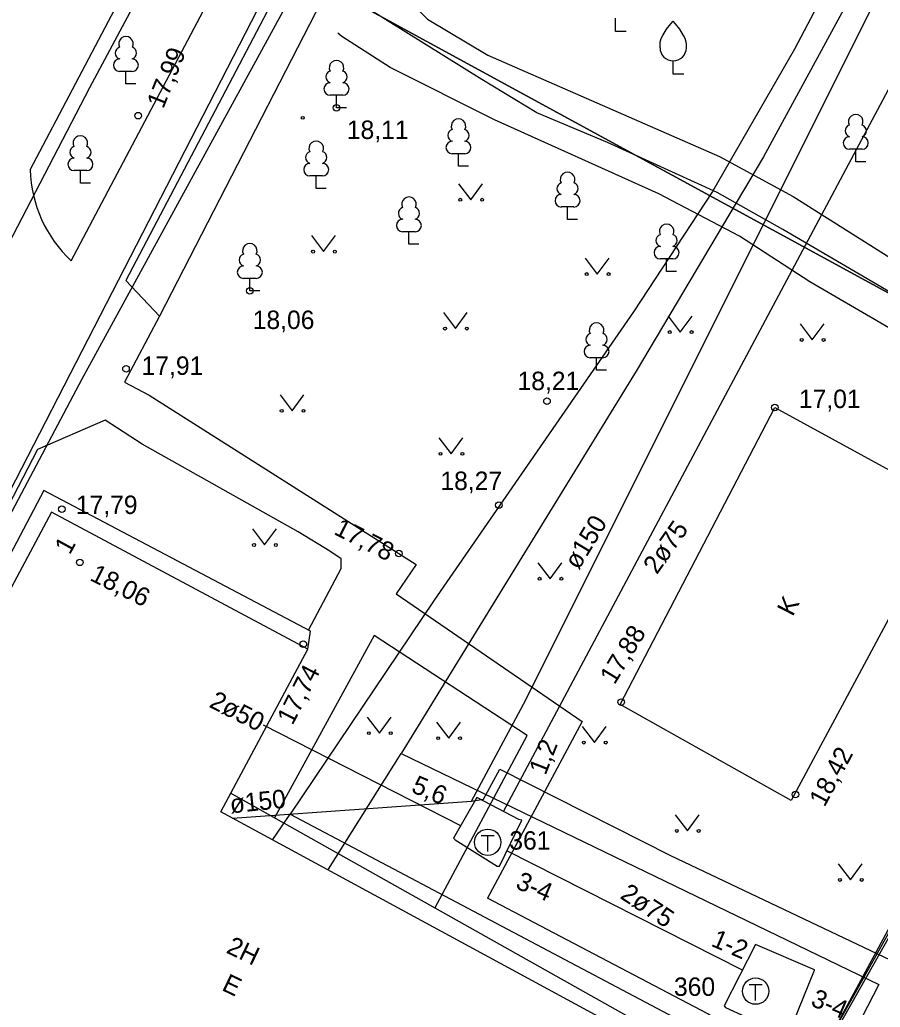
# Model space of a CAD drawing. Extents: x 713540 to 713867, y 6589774 to 6590061.
# Drawn here: x 713743.37 to 713776.03, y 6589910.9 to 6589948.37 of the extents above; entities that cross this region are included whole.
import ezdxf

# ---------------------------------------------------------------- set-up
doc = ezdxf.new("R2010")
doc.units = 0
for name, color, linetype in [('AED', 7, 'Continuous'), ('HALJASTUS', 7, 'Continuous'), ('HOONE', 7, 'Continuous'), ('KORGUS', 7, 'Continuous'), ('MPKAABEL', 7, 'Continuous'), ('PUU', 7, 'Continuous'), ('SIKAEV', 7, 'Continuous'), ('SITRASS', 7, 'Continuous'), ('TEE', 7, 'Continuous'), ('TKAEV', 7, 'Continuous'), ('TORU NR', 7, 'Continuous'), ('TTRASS', 7, 'Continuous'), ('VTRASS', 7, 'Continuous'), ('По умолчанию', 7, 'Continuous'), ('Слой 1', 7, 'Continuous')]:
    doc.layers.add(name, color=color, linetype=linetype)

msp = doc.modelspace()

# ---------------------------------------------------------------- linework, layer by layer
at = {"layer": 'AED'}
for points in [[(713767.762, 6589909.249), (713772.443, 6589906.664), (713772.921, 6589907.533), (713780.72, 6589921.96), (713784.33, 6589929.01), (713786.08, 6589932.05), (713790.79, 6589929.6), (713799.05, 6589941.64), (713799.92, 6589942.78), (713800.93, 6589944.67), (713803.18, 6589949.29), (713806.07, 6589954.43), (713810.4, 6589962.76), (713799.4, 6589967.72), (713795.11, 6589969.78), (713786.56, 6589953.97)], [(713763.714, 6589966.383), (713748.668, 6589937.119)]]:
    msp.add_lwpolyline(points, dxfattribs=at)
at = {"layer": 'HALJASTUS'}
for p, q in [((713760.027, 6589942.147), (713760.49, 6589941.54)), ((713760.49, 6589941.54), (713760.936, 6589942.147)), ((713754.437, 6589940.177), (713754.9, 6589939.57)), ((713754.9, 6589939.57), (713755.346, 6589940.177)), ((713764.827, 6589939.327), (713765.29, 6589938.72)), ((713765.29, 6589938.72), (713765.736, 6589939.327)), ((713759.447, 6589937.257), (713759.91, 6589936.65)), ((713759.91, 6589936.65), (713760.356, 6589937.257)), ((713767.977, 6589937.127), (713768.44, 6589936.52)), ((713768.44, 6589936.52), (713768.886, 6589937.127)), ((713772.987, 6589936.827), (713773.45, 6589936.22)), ((713773.45, 6589936.22), (713773.896, 6589936.827)), ((713753.247, 6589934.137), (713753.71, 6589933.53)), ((713753.71, 6589933.53), (713754.156, 6589934.137)), ((713759.277, 6589932.507), (713759.74, 6589931.9)), ((713759.74, 6589931.9), (713760.186, 6589932.507)), ((713752.197, 6589929.047), (713752.66, 6589928.44)), ((713752.66, 6589928.44), (713753.106, 6589929.047)), ((713763.037, 6589927.767), (713763.5, 6589927.16)), ((713763.5, 6589927.16), (713763.946, 6589927.767)), ((713756.557, 6589921.907), (713757.02, 6589921.3)), ((713757.02, 6589921.3), (713757.466, 6589921.907)), ((713759.187, 6589921.717), (713759.65, 6589921.11)), ((713759.65, 6589921.11), (713760.096, 6589921.717)), ((713764.717, 6589921.547), (713765.18, 6589920.94)), ((713765.18, 6589920.94), (713765.626, 6589921.547)), ((713768.247, 6589918.197), (713768.71, 6589917.59)), ((713768.71, 6589917.59), (713769.156, 6589918.197)), ((713774.437, 6589916.337), (713774.9, 6589915.73)), ((713774.9, 6589915.73), (713775.346, 6589916.337))]:
    msp.add_line(p, q, dxfattribs=at)
for points in [[(713760.304, 6589956.722), (713758.16, 6589952.94), (713757.47, 6589951.68), (713757.33, 6589950.37), (713757.8, 6589949.47), (713758.84, 6589948.39), (713761.14, 6589947.03), (713764.66, 6589945.48), (713769.93, 6589943.18), (713772.72, 6589941.66), (713777.94, 6589938.37), (713784.38, 6589934.37), (713785.89, 6589933.2), (713785.84, 6589932.59), (713785.7, 6589931.83)], [(713784.59, 6589933.17), (713781.02, 6589935.33), (713772.33, 6589940.41), (713769.84, 6589941.82), (713765.68, 6589943.71), (713762.99, 6589944.84), (713760.91, 6589946.1), (713756.58, 6589948.8), (713756.13, 6589949.298)], [(713785.7, 6589931.83), (713779.9, 6589934.62), (713773.36, 6589938.43), (713770.69, 6589940.16), (713767.63, 6589941.77), (713761.39, 6589944.57), (713757.43, 6589946.56), (713755.59, 6589947.74), (713755.446, 6589947.863)]]:
    msp.add_lwpolyline(points, dxfattribs=at)
for centre in [(713760.089, 6589941.54), (713760.918, 6589941.54), (713754.499, 6589939.57), (713755.328, 6589939.57), (713764.889, 6589938.72), (713765.718, 6589938.72), (713759.509, 6589936.65), (713760.338, 6589936.65), (713768.039, 6589936.52), (713768.868, 6589936.52), (713773.049, 6589936.22), (713773.878, 6589936.22), (713753.309, 6589933.53), (713754.138, 6589933.53), (713759.339, 6589931.9), (713760.168, 6589931.9), (713752.259, 6589928.44), (713753.088, 6589928.44), (713763.099, 6589927.16), (713763.928, 6589927.16), (713756.619, 6589921.3), (713757.448, 6589921.3), (713759.249, 6589921.11), (713760.078, 6589921.11), (713764.779, 6589920.94), (713765.608, 6589920.94), (713768.309, 6589917.59), (713769.138, 6589917.59), (713774.499, 6589915.73), (713775.328, 6589915.73)]:
    msp.add_circle(centre, 0.055, dxfattribs=at)
at = {"layer": 'HOONE'}
for points in [[(713760.52, 6589918.72), (713762.58, 6589922.57), (713777.85, 6589953.12)], [(713772.03, 6589933.66), (713778.7, 6589930.01), (713778.64, 6589929.91), (713772.65, 6589918.74), (713766.16, 6589922.39), (713772.03, 6589933.66)], [(713767.753, 6589909.232), (713751, 6589918.31), (713754.305, 6589924.488), (713744.575, 6589929.68), (713736.017, 6589913.674), (713762.631, 6589899.577), (713767.753, 6589909.232)], [(713760.52, 6589918.72), (713760.97, 6589918.8), (713761.59, 6589919.93), (713768.07, 6589916.66), (713778.69, 6589911.61), (713767.43, 6589890.63), (713753, 6589864.84), (713751.627, 6589862.341)], [(713751.44, 6589918.07), (713760.52, 6589918.72)]]:
    msp.add_lwpolyline(points, dxfattribs=at)
at = {"layer": 'KORGUS'}
for centre in [(713755.39, 6589945.03), (713747.86, 6589944.73), (713752.1, 6589938.08), (713747.4, 6589935.12), (713763.38, 6589933.9), (713772.03, 6589933.66), (713761.55, 6589929.95), (713744.96, 6589929.8), (713757.76, 6589928.12), (713745.65, 6589927.78), (713754.13, 6589924.68), (713766.2, 6589922.48), (713772.81, 6589918.97)]:
    msp.add_circle(centre, 0.125, dxfattribs=at)
at = {"layer": 'MPKAABEL'}
for points in [[(713732.905, 6589979.347), (713738.612, 6589976.697), (713744.311, 6589973.432), (713750.492, 6589970.566), (713758.7, 6589965.226), (713761.213, 6589964.896), (713763.366, 6589965.211), (713774.093, 6589959.513), (713777.1, 6589957.91), (713777.68, 6589957.38), (713777.72, 6589957.03), (713777.72, 6589956.58), (713777.41, 6589956.05), (713772.78, 6589947.26), (713769.66, 6589941.85), (713766.66, 6589937.29), (713759.1, 6589926.34), (713753.63, 6589918.22)], [(713753.63, 6589918.22), (713768.19, 6589910.52), (713768.88, 6589910.17), (713769.18, 6589909.51), (713769.069, 6589909.29), (713768.993, 6589909.14), (713753.23, 6589877.99), (713756.95, 6589876.35), (713752.899, 6589868.247), (713751.951, 6589868.518)], [(713752.97, 6589917.26), (713753.63, 6589918.22)]]:
    msp.add_lwpolyline(points, dxfattribs=at)
at = {"layer": 'PUU'}
for p, q in [((713765.98, 6589947.93), (713765.98, 6589948.43)), ((713766.38, 6589947.93), (713765.98, 6589947.93)), ((713768.17, 6589946.31), (713768.17, 6589946.81)), ((713747.637, 6589946.41), (713747.157, 6589946.41)), ((713747.397, 6589945.935), (713747.397, 6589946.41)), ((713768.57, 6589946.31), (713768.17, 6589946.31)), ((713747.777, 6589945.935), (713747.397, 6589945.935)), ((713755.63, 6589945.505), (713755.15, 6589945.505)), ((713755.39, 6589945.03), (713755.39, 6589945.505)), ((713755.77, 6589945.03), (713755.39, 6589945.03)), ((713760.26, 6589943.285), (713759.78, 6589943.285)), ((713760.02, 6589942.81), (713760.02, 6589943.285)), ((713775.34, 6589943.455), (713774.86, 6589943.455)), ((713775.1, 6589942.98), (713775.1, 6589943.455)), ((713760.4, 6589942.81), (713760.02, 6589942.81)), ((713775.48, 6589942.98), (713775.1, 6589942.98)), ((713745.909, 6589942.645), (713745.429, 6589942.645)), ((713745.669, 6589942.17), (713745.669, 6589942.645)), ((713754.86, 6589942.445), (713754.38, 6589942.445)), ((713754.62, 6589941.97), (713754.62, 6589942.445)), ((713746.049, 6589942.17), (713745.669, 6589942.17)), ((713755, 6589941.97), (713754.62, 6589941.97)), ((713764.4, 6589941.265), (713763.92, 6589941.265)), ((713764.16, 6589940.79), (713764.16, 6589941.265)), ((713764.54, 6589940.79), (713764.16, 6589940.79)), ((713758.38, 6589940.325), (713757.9, 6589940.325)), ((713758.14, 6589939.85), (713758.14, 6589940.325)), ((713758.52, 6589939.85), (713758.14, 6589939.85)), ((713768.16, 6589939.295), (713767.68, 6589939.295)), ((713767.92, 6589938.82), (713767.92, 6589939.295)), ((713768.3, 6589938.82), (713767.92, 6589938.82)), ((713752.34, 6589938.555), (713751.86, 6589938.555)), ((713752.1, 6589938.08), (713752.1, 6589938.555)), ((713752.48, 6589938.08), (713752.1, 6589938.08)), ((713765.5, 6589935.545), (713765.02, 6589935.545)), ((713765.26, 6589935.07), (713765.26, 6589935.545)), ((713765.64, 6589935.07), (713765.26, 6589935.07))]:
    msp.add_line(p, q, dxfattribs=at)
for points in [[(713767.67, 6589947.31), (713767.67, 6589947.46), (713767.68, 6589947.525), (713767.715, 6589947.655), (713767.775, 6589947.775), (713767.92, 6589948.01), (713768.08, 6589948.215), (713768.17, 6589948.31)], [(713768.67, 6589947.31), (713768.67, 6589947.46), (713768.66, 6589947.525), (713768.625, 6589947.655), (713768.565, 6589947.775), (713768.42, 6589948.01), (713768.26, 6589948.215), (713768.17, 6589948.31)]]:
    msp.add_lwpolyline(points, dxfattribs=at)
for centre, radius, start, end in [((713747.397, 6589947.455), 0.277, 332.5799, 207.4201), ((713747.227, 6589947.108), 0.233, 109.0217, 253.1415), ((713747.567, 6589947.108), 0.233, 286.8508, 70.9859), ((713768.17, 6589947.31), 0.5, 180, 0), ((713747.159, 6589946.648), 0.238, 90.0016, 269.3953), ((713747.634, 6589946.648), 0.238, 270.6047, 89.9984), ((713755.39, 6589946.55), 0.277, 332.5799, 207.4201), ((713755.22, 6589946.203), 0.233, 109.0217, 253.1415), ((713755.56, 6589946.203), 0.233, 286.8508, 70.9859), ((713755.153, 6589945.742), 0.238, 90.0016, 269.3953), ((713755.627, 6589945.742), 0.238, 270.6047, 89.9984), ((713775.1, 6589944.5), 0.277, 332.5799, 207.4201), ((713760.02, 6589944.33), 0.277, 332.5799, 207.4201), ((713774.93, 6589944.153), 0.233, 109.0217, 253.1415), ((713775.27, 6589944.153), 0.233, 286.8508, 70.9859), ((713745.669, 6589943.69), 0.277, 332.5799, 207.4201), ((713759.85, 6589943.983), 0.233, 109.0217, 253.1415), ((713760.19, 6589943.983), 0.233, 286.8508, 70.9859), ((713774.863, 6589943.692), 0.238, 90.0016, 269.3953), ((713775.337, 6589943.692), 0.238, 270.6047, 89.9984), ((713745.499, 6589943.343), 0.233, 109.0217, 253.1415), ((713745.839, 6589943.343), 0.233, 286.8508, 70.9859), ((713754.62, 6589943.49), 0.277, 332.5799, 207.4201), ((713759.783, 6589943.522), 0.238, 90.0016, 269.3953), ((713760.257, 6589943.522), 0.238, 270.6047, 89.9984), ((713754.45, 6589943.143), 0.233, 109.0217, 253.1415), ((713754.79, 6589943.143), 0.233, 286.8508, 70.9859), ((713745.431, 6589942.883), 0.238, 90.0016, 269.3953), ((713745.906, 6589942.883), 0.238, 270.6047, 89.9984), ((713754.383, 6589942.682), 0.238, 90.0016, 269.3953), ((713754.857, 6589942.682), 0.238, 270.6047, 89.9984), ((713764.16, 6589942.31), 0.277, 332.5799, 207.4201), ((713763.99, 6589941.963), 0.233, 109.0217, 253.1415), ((713764.33, 6589941.963), 0.233, 286.8508, 70.9859), ((713763.923, 6589941.502), 0.238, 90.0016, 269.3953), ((713764.397, 6589941.502), 0.238, 270.6047, 89.9984), ((713758.14, 6589941.37), 0.277, 332.5799, 207.4201), ((713757.97, 6589941.023), 0.233, 109.0217, 253.1415), ((713758.31, 6589941.023), 0.233, 286.8508, 70.9859), ((713757.903, 6589940.562), 0.238, 90.0016, 269.3953), ((713758.377, 6589940.562), 0.238, 270.6047, 89.9984), ((713767.92, 6589940.34), 0.277, 332.5799, 207.4201), ((713767.75, 6589939.993), 0.233, 109.0217, 253.1415), ((713768.09, 6589939.993), 0.233, 286.8508, 70.9859), ((713752.1, 6589939.6), 0.277, 332.5799, 207.4201), ((713751.93, 6589939.253), 0.233, 109.0217, 253.1415), ((713752.27, 6589939.253), 0.233, 286.8508, 70.9859), ((713767.683, 6589939.532), 0.238, 90.0016, 269.3953), ((713768.157, 6589939.532), 0.238, 270.6047, 89.9984), ((713751.863, 6589938.792), 0.238, 90.0016, 269.3953), ((713752.337, 6589938.792), 0.238, 270.6047, 89.9984), ((713765.26, 6589936.59), 0.277, 332.5799, 207.4201), ((713765.09, 6589936.243), 0.233, 109.0217, 253.1415), ((713765.43, 6589936.243), 0.233, 286.8508, 70.9859), ((713765.023, 6589935.782), 0.238, 90.0016, 269.3953), ((713765.497, 6589935.782), 0.238, 270.6047, 89.9984)]:
    msp.add_arc(centre, radius, start, end, dxfattribs=at)
at = {"layer": 'SITRASS'}
for points in [[(713784.17, 6589966.48), (713783.15, 6589964.52), (713775.28, 6589949.95), (713771.6, 6589943.17), (713766.77, 6589935.04), (713757.84, 6589920.53)], [(713733.955, 6589912.506), (713745.74, 6589934.74), (713757.595, 6589956.438)], [(713755.08, 6589916.14), (713757.84, 6589920.53)], [(713757.84, 6589920.53), (713775.98, 6589911.76)], [(713775.98, 6589911.76), (713773.604, 6589907.17), (713773.451, 6589906.873), (713751.23, 6589863.94), (713743.875, 6589867.46), (713727.91, 6589875.1), (713724.68, 6589872.85), (713726.93, 6589859.54), (713725.61, 6589859.29)]]:
    msp.add_lwpolyline(points, dxfattribs=at)
at = {"layer": 'TEE'}
for points in [[(713745.323, 6589939.226), (713759.427, 6589965.904), (713771.434, 6589988.676), (713771.387, 6589989.539)], [(713743.761, 6589942.675), (713757.248, 6589968.279), (713767.715, 6589988.031), (713768.327, 6589988.929)], [(713773.399, 6589987.91), (713761.879, 6589966.052), (713747.389, 6589938.479), (713748.668, 6589937.119), (713747.341, 6589934.622), (713748.274, 6589934.123), (713758.415, 6589927.701), (713757.661, 6589926.588), (713764.712, 6589921.738), (713761.12, 6589915.04)], [(713754.325, 6589925.207), (713755.57, 6589927.55), (713755.57, 6589927.91), (713755.14, 6589928.21), (713753.94, 6589928.94), (713748.018, 6589932.271), (713746.604, 6589933.172), (713744.042, 6589932.066), (713734.222, 6589913.122), (713735.109, 6589911.505), (713736.436, 6589909.083), (713765.187, 6589894.737)], [(713754.305, 6589924.488), (713754.401, 6589925.167), (713744.284, 6589930.51), (713735.234, 6589913.331), (713736.747, 6589912.529)], [(713759.121, 6589914.663), (713762.621, 6589921.215), (713756.819, 6589924.999), (713753.033, 6589918.081)], [(713736.747, 6589912.529), (713762.965, 6589898.641), (713768.632, 6589909.323), (713751.363, 6589919.019)], [(713769.923, 6589909.03), (713770.02, 6589909.23), (713770.13, 6589909.81), (713770.02, 6589910.27), (713769.48, 6589910.65), (713761.12, 6589915.04)]]:
    msp.add_lwpolyline(points, dxfattribs=at)
msp.add_arc((713748.639, 6589942.806), 4.879, 181.5343, 227.1882, dxfattribs=at)
at = {"layer": 'TKAEV'}
for p, q in [((713760.88, 6589917.41), (713761.38, 6589917.41)), ((713761.13, 6589916.81), (713761.13, 6589917.41)), ((713771.05, 6589911.76), (713771.55, 6589911.76)), ((713771.3, 6589911.16), (713771.3, 6589911.76))]:
    msp.add_line(p, q, dxfattribs=at)
for centre in [(713761.13, 6589917.16), (713771.3, 6589911.51)]:
    msp.add_circle(centre, 0.5, dxfattribs=at)
at = {"layer": 'TTRASS'}
for points in [[(713761.73, 6589918.33), (713786.89, 6589965.52)], [(713752.6, 6589921.61), (713760.1, 6589917.79)], [(713760.72, 6589918.86), (713759.83, 6589917.32), (713759.9, 6589917.25), (713761.49, 6589916.25), (713761.58, 6589916.25), (713762.42, 6589918), (713762.31, 6589918.02), (713760.72, 6589918.86)], [(713770.8, 6589912.3), (713761.86, 6589916.84)], [(713771.3, 6589913.28), (713770.1, 6589910.95), (713770.16, 6589910.89), (713772.45, 6589909.84), (713772.54, 6589909.84), (713773.53, 6589912.3), (713773.53, 6589912.32), (713771.3, 6589913.28)]]:
    msp.add_lwpolyline(points, dxfattribs=at)
at = {"layer": 'VTRASS'}
msp.add_lwpolyline([(713786.9, 6590022.053), (713786.663, 6590021.42), (713779.918, 6590009.263), (713774.768, 6590000.13), (713772.089, 6589995.293), (713771.2, 6589993.262), (713769.595, 6589990.576), (713766.999, 6589985.749), (713760.969, 6589973.854), (713754.105, 6589960.72), (713753.933, 6589960.165), (713750.695, 6589954.533), (713746.011, 6589945.782), (713740.356, 6589934.918), (713733.16, 6589921.546), (713727.052, 6589912.116), (713721.352, 6589902.724), (713721.093, 6589902.329)], dxfattribs=at)
at = {"layer": 'По умолчанию'}
msp.add_circle((713754.108, 6589944.65), 0.055, dxfattribs=at)
at = {"layer": 'Слой 1'}
for points in [[(713800.41, 6589978.59), (713796.9, 6589972.02), (713811.25, 6589964.46), (713800.51, 6589942.86), (713790.89, 6589929.51), (713786.76, 6589932.33), (713753.32, 6589950.56), (713774.49, 6589992.04)], [(713753.32, 6589950.56), (713786.76, 6589932.33), (713765.63, 6589894.55), (713732.87, 6589910.81)], [(713801.77, 6589877.49), (713765.63, 6589894.55), (713785.68, 6589930.05), (713821.49, 6589913.26)]]:
    msp.add_lwpolyline(points, close=True, dxfattribs=at)

# ---------------------------------------------------------------- texts
at = {"layer": 'HOONE'}
for s, rotation, p in [('1', 61.4199, (713745.266, 6589928.041)), ('K', 62.8886, (713772.704, 6589925.699)), ('2H', 334.532, (713751.167, 6589912.983)), ('E', 334.532, (713750.998, 6589911.562))]:
    msp.add_text(s, height=0.7, rotation=rotation, dxfattribs=at).set_placement(p)
at = {"layer": 'KORGUS'}
for s, rotation, p in [('17,99', 68.1509, (713748.814, 6589944.963)), ('17,78', 332.9938, (713755.253, 6589928.869)), ('18,06', 333.435, (713745.987, 6589927.119)), ('17,88', 58.7204, (713765.943, 6589923.112)), ('17,74', 62.8637, (713753.72, 6589921.57)), ('18,42', 61.8025, (713773.912, 6589918.463))]:
    msp.add_text(s, height=0.7, rotation=rotation, dxfattribs=at).set_placement(p)
for s, p in [('18,11', (713755.782, 6589943.845)), ('18,06', (713752.21, 6589936.635)), ('17,91', (713747.992, 6589934.895)), ('18,21', (713762.262, 6589934.315)), ('17,01', (713772.942, 6589933.635)), ('18,27', (713759.333, 6589930.525)), ('17,79', (713745.496, 6589929.615))]:
    msp.add_text(s, height=0.7, dxfattribs=at).set_placement(p)
at = {"layer": 'SIKAEV'}
for s, p in [('361', (713761.95, 6589916.88)), ('360', (713768.2, 6589911.33))]:
    msp.add_text(s, height=0.7, dxfattribs=at).set_placement(p)
at = {"layer": 'TORU NR'}
for s, rotation, p in [('ø150', 58.7707, (713764.582, 6589927.464)), ('2ø75', 55.0036, (713767.552, 6589927.294)), ('2ø50', 332.9695, (713750.519, 6589922.311)), ('1,2', 68.4714, (713763.323, 6589919.674)), ('5,6', 336.7779, (713758.191, 6589919.078)), ('ø150', 6.0077, (713751.376, 6589918.253)), ('3-4', 336.7779, (713762.151, 6589915.428)), ('2ø75', 326.5409, (713766.118, 6589915.059)), ('1-2', 336.7779, (713769.571, 6589913.238)), ('3-4', 336.7779, (713773.351, 6589910.978))]:
    msp.add_text(s, height=0.7, rotation=rotation, dxfattribs=at).set_placement(p)

doc.saveas('drawing.dxf')
